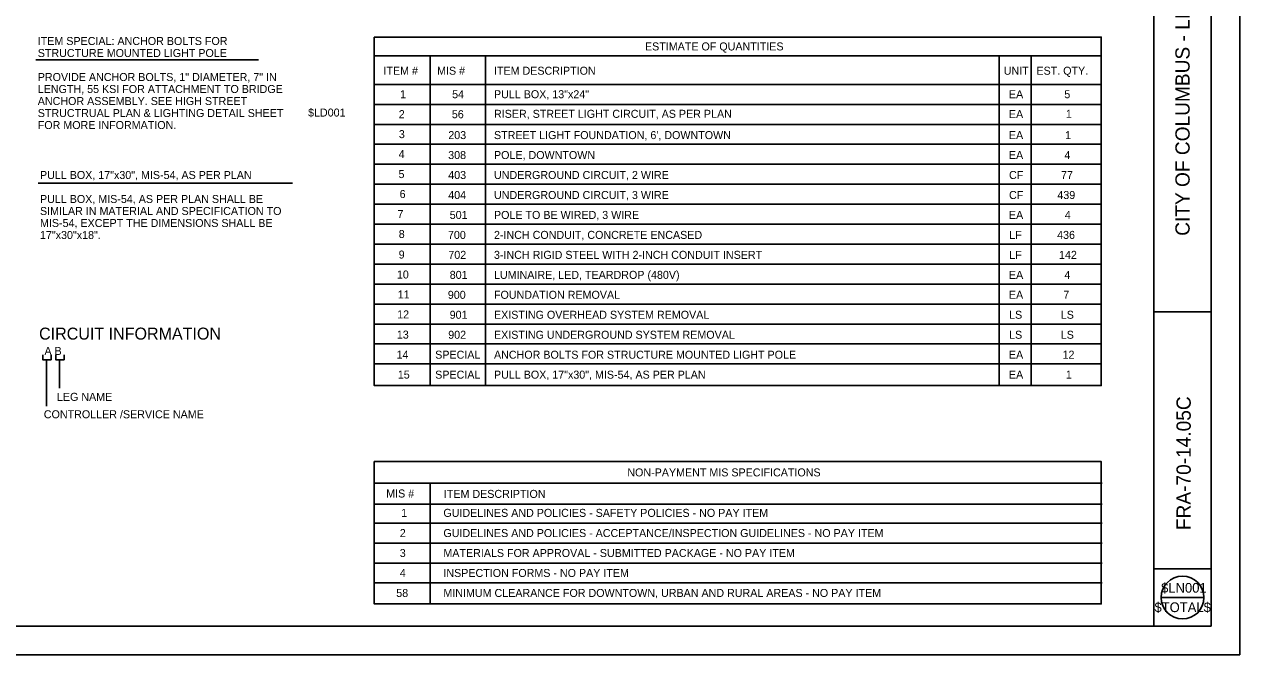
# Model space of a CAD drawing. Extents: x 0 to 34, y 0 to 22.
# Drawn here: x 12.74 to 34, y 0 to 11.03 of the extents above; entities that cross this region are included whole.
import ezdxf

# ---------------------------------------------------------------- set-up
doc = ezdxf.new("R2010")
doc.units = 0
for name, color, linetype in [('LT_P_Text', 7, 'Continuous'), ('SH_Border', 7, 'Continuous'), ('SH_Cut_Line', 7, 'Continuous'), ('SH_Data', 7, 'Continuous')]:
    doc.layers.add(name, color=color, linetype=linetype)

msp = doc.modelspace()

# ---------------------------------------------------------------- linework, layer by layer
at = {"layer": 'LT_P_Text'}
for p, q in [((18.863, 10.477), (31.58, 10.477)), ((19.839, 10.477), (19.839, 4.709)), ((20.808, 10.477), (20.808, 4.709)), ((29.793, 10.477), (29.793, 4.709)), ((30.354, 10.477), (30.354, 4.709)), ((12.945, 10.409), (16.838, 10.409)), ((18.863, 9.976), (31.58, 9.976)), ((18.863, 9.627), (31.58, 9.627)), ((18.863, 9.278), (31.58, 9.278)), ((18.863, 9.278), (31.58, 9.278)), ((18.863, 8.929), (31.58, 8.929)), ((18.863, 8.579), (31.58, 8.579)), ((12.984, 8.249), (17.436, 8.249)), ((18.863, 8.23), (31.58, 8.23)), ((18.863, 7.881), (31.58, 7.881)), ((18.863, 7.532), (31.58, 7.532)), ((18.863, 7.182), (31.58, 7.182)), ((18.863, 6.833), (31.58, 6.833)), ((18.863, 6.484), (31.58, 6.484)), ((18.863, 6.484), (31.58, 6.484)), ((18.863, 6.134), (31.58, 6.134)), ((18.863, 5.785), (31.58, 5.785)), ((18.863, 5.436), (31.58, 5.436)), ((13.134, 5.16), (13.134, 4.349)), ((13.362, 5.16), (13.362, 4.661)), ((18.863, 5.087), (31.58, 5.087)), ((18.863, 3.002), (31.593, 3.002)), ((19.839, 0.888), (19.839, 3.002)), ((18.863, 2.633), (31.593, 2.633)), ((18.863, 2.303), (31.593, 2.303)), ((18.863, 1.954), (31.593, 1.954)), ((18.863, 1.604), (31.593, 1.604)), ((18.863, 1.255), (31.593, 1.255))]:
    msp.add_line(p, q, dxfattribs=at)
for points in [[(18.863, 10.805), (31.58, 10.805), (31.58, 4.709), (18.863, 4.709)], [(18.863, 3.379), (31.58, 3.379), (31.58, 0.888), (18.863, 0.888)]]:
    msp.add_lwpolyline(points, close=True, dxfattribs=at)
for points in [[(13.066, 5.245), (13.066, 5.16), (13.211, 5.16), (13.211, 5.246)], [(13.295, 5.245), (13.295, 5.16), (13.44, 5.16), (13.44, 5.246)]]:
    msp.add_lwpolyline(points, dxfattribs=at)
at = {"layer": 'SH_Border'}
for p, q in [((32.5, 0.5), (32.5, 21.5)), ((32.5, 6), (33.5, 6)), ((32.5, 1.5), (33.5, 1.5))]:
    msp.add_line(p, q, dxfattribs=at)
msp.add_lwpolyline([(2, 21.5), (33.5, 21.5), (33.5, 0.5), (2, 0.5)], close=True, dxfattribs=at)
at = {"layer": 'SH_Cut_Line'}
msp.add_lwpolyline([(0, 0), (34, 0), (34, 22), (0, 22)], close=True, dxfattribs=at)
at = {"layer": 'SH_Data'}
msp.add_line((32.625, 1), (33.375, 1), dxfattribs=at)
msp.add_circle((33, 1), 0.375, dxfattribs=at)

# ---------------------------------------------------------------- texts
at = {"layer": 'LT_P_Text'}
for s, height, rotation, p in [('ITEM SPECIAL: ANCHOR BOLTS FOR ', 0.14, 360, (12.979, 10.666)), ('STRUCTURE MOUNTED LIGHT POLE', 0.14, 360, (12.979, 10.456)), ('PROVIDE ANCHOR BOLTS, 1" DIAMETER, 7" IN ', 0.14, 360, (12.979, 10.036)), ('LENGTH, 55 KSI FOR ATTACHMENT TO BRIDGE ', 0.14, 360, (12.979, 9.826)), ('ANCHOR ASSEMBLY. SEE HIGH STREET ', 0.14, 360, (12.979, 9.616)), ('STRUCTRUAL PLAN & LIGHTING DETAIL SHEET          ', 0.14, 360, (12.979, 9.406)), ('FOR MORE INFORMATION.', 0.14, 360, (12.979, 9.196)), ('PULL BOX, 17"x30", MIS-54, AS PER PLAN', 0.14, 360, (13.018, 8.322)), ('PULL BOX, MIS-54, AS PER PLAN SHALL BE ', 0.14, 360, (13.018, 7.902)), ('SIMILAR IN MATERIAL AND SPECIFICATION TO ', 0.14, 360, (13.018, 7.692)), ('MIS-54, EXCEPT THE DIMENSIONS SHALL BE ', 0.14, 360, (13.018, 7.482)), ('17"x30"x18".', 0.14, 360, (13.018, 7.272)), ('FRA-70-14.05C', 0.24987, 90, (33.144, 2.18))]:
    msp.add_text(s, height=height, rotation=rotation, dxfattribs=at).set_placement(p)
for s, height, p in [('ESTIMATE OF QUANTITIES', 0.14, (23.599, 10.571)), ('ITEM #', 0.14, (19.025, 10.146)), ('MIS #', 0.14, (19.963, 10.146)), ('ITEM DESCRIPTION', 0.14, (20.958, 10.146)), ('UNIT', 0.14, (29.873, 10.146)), ('EST. QTY.', 0.14, (30.445, 10.146)), ('1', 0.14, (19.316, 9.735)), ('54', 0.14, (20.226, 9.735)), ('PULL BOX, 13"x24"', 0.14, (20.958, 9.735)), ('EA', 0.14, (29.964, 9.735)), ('5', 0.14, (30.933, 9.735)), ('$LD001', 0.14, (17.706, 9.414)), ('2', 0.14, (19.292, 9.386)), ('56', 0.14, (20.221, 9.385)), ('RISER, STREET LIGHT CIRCUIT, AS PER PLAN', 0.14, (20.958, 9.392)), ('EA', 0.14, (29.964, 9.387)), ('1', 0.14, (30.959, 9.392)), ('3', 0.14, (19.294, 9.037)), ('203', 0.14, (20.159, 9.02)), ("STREET LIGHT FOUNDATION, 6', DOWNTOWN", 0.14, (20.958, 9.02)), ('EA', 0.14, (29.964, 9.02)), ('1', 0.14, (30.947, 9.02)), ('4', 0.14, (19.29, 8.687)), ('308', 0.14, (20.157, 8.671)), ('POLE, DOWNTOWN', 0.14, (20.958, 8.671)), ('EA', 0.14, (29.964, 8.671)), ('4', 0.14, (30.935, 8.671)), ('5', 0.14, (19.288, 8.338)), ('403', 0.14, (20.158, 8.322)), ('UNDERGROUND CIRCUIT, 2 WIRE', 0.14, (20.958, 8.322)), ('CF', 0.14, (29.966, 8.322)), ('77', 0.14, (30.875, 8.322)), ('6', 0.14, (19.308, 7.989)), ('404', 0.14, (20.158, 7.972)), ('UNDERGROUND CIRCUIT, 3 WIRE', 0.14, (20.958, 7.972)), ('CF', 0.14, (29.966, 7.972)), ('439', 0.14, (30.811, 7.972)), ('7', 0.14, (19.27, 7.639)), ('501', 0.14, (20.184, 7.623)), ('POLE TO BE WIRED, 3 WIRE', 0.14, (20.958, 7.623)), ('EA', 0.14, (29.964, 7.623)), ('4', 0.14, (30.941, 7.623)), ('8', 0.14, (19.292, 7.29)), ('700', 0.14, (20.153, 7.274)), ('2-INCH CONDUIT, CONCRETE ENCASED', 0.14, (20.958, 7.274)), ('LF', 0.14, (29.97, 7.274)), ('436', 0.14, (30.807, 7.274)), ('9', 0.14, (19.291, 6.93)), ('702', 0.14, (20.16, 6.925)), ('3-INCH RIGID STEEL WITH 2-INCH CONDUIT INSERT', 0.14, (20.958, 6.925)), ('LF', 0.14, (29.97, 6.925)), ('142', 0.14, (30.84, 6.925)), ('10', 0.14, (19.26, 6.581)), ('801', 0.14, (20.184, 6.575)), ('LUMINAIRE, LED, TEARDROP (480V)', 0.14, (20.958, 6.575)), ('EA', 0.14, (29.964, 6.575)), ('4', 0.14, (30.935, 6.575)), ('11', 0.14, (19.275, 6.232)), ('900', 0.14, (20.151, 6.226)), ('FOUNDATION REMOVAL', 0.14, (20.958, 6.226)), ('EA', 0.14, (29.964, 6.226)), ('7', 0.14, (30.915, 6.226)), ('12', 0.14, (19.265, 5.883)), ('901', 0.14, (20.183, 5.877)), ('EXISTING OVERHEAD SYSTEM REMOVAL', 0.14, (20.958, 5.877)), ('LS', 0.14, (29.967, 5.877)), ('LS', 0.14, (30.871, 5.877)), ('CIRCUIT INFORMATION', 0.21, (13.002, 5.512)), ('13', 0.14, (19.259, 5.53)), ('902', 0.14, (20.158, 5.527)), ('EXISTING UNDERGROUND SYSTEM REMOVAL', 0.14, (20.958, 5.527)), ('LS', 0.14, (29.967, 5.527)), ('LS', 0.14, (30.871, 5.527)), ('A B ', 0.14, (13.096, 5.244)), ('14', 0.14, (19.254, 5.179)), ('SPECIAL', 0.14, (19.93, 5.178)), ('ANCHOR BOLTS FOR STRUCTURE MOUNTED LIGHT POLE', 0.14, (20.958, 5.178)), ('EA', 0.14, (29.964, 5.178)), ('12', 0.14, (30.902, 5.178)), ('15', 0.14, (19.276, 4.83)), ('SPECIAL', 0.14, (19.93, 4.829)), ('PULL BOX, 17"x30", MIS-54, AS PER PLAN', 0.14, (20.958, 4.829)), ('EA', 0.14, (29.964, 4.829)), ('1', 0.14, (30.959, 4.829)), ('LEG NAME', 0.14, (13.314, 4.441)), ('CONTROLLER /SERVICE NAME', 0.14, (13.085, 4.136)), ('NON-PAYMENT MIS SPECIFICATIONS', 0.14, (23.29, 3.119)), ('MIS #', 0.14, (19.073, 2.75)), ('ITEM DESCRIPTION', 0.14, (20.081, 2.743)), ('1', 0.14, (19.335, 2.411)), ('GUIDELINES AND POLICIES - SAFETY POLICIES - NO PAY ITEM', 0.14, (20.073, 2.411)), ('2', 0.14, (19.311, 2.058)), ('GUIDELINES AND POLICIES - ACCEPTANCE/INSPECTION GUIDELINES - NO PAY ITEM', 0.14, (20.073, 2.058)), ('3', 0.14, (19.31, 1.709)), ('MATERIALS FOR APPROVAL - SUBMITTED PACKAGE - NO PAY ITEM', 0.14, (20.073, 1.709)), ('4', 0.14, (19.311, 1.36)), ('INSPECTION FORMS - NO PAY ITEM', 0.14, (20.073, 1.36)), ('58', 0.14, (19.249, 1.01)), ('MINIMUM CLEARANCE FOR DOWNTOWN, URBAN AND RURAL AREAS - NO PAY ITEM', 0.14, (20.073, 1.01))]:
    msp.add_text(s, height=height, dxfattribs=at).set_placement(p)
at = {"layer": 'SH_Data'}
msp.add_text(' CITY OF COLUMBUS - LIGHTING GENERAL NOTES  ', height=0.25, rotation=90, dxfattribs=at).set_placement((33.125, 7.235))
for s, p in [('$LN001', (32.626, 1.085)), ('$TOTAL$', (32.51, 0.745))]:
    msp.add_text(s, height=0.17, dxfattribs=at).set_placement(p)

doc.saveas('drawing.dxf')
